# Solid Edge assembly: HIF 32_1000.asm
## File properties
Title: Zylinder
Author: ahadarics
Template: iso assembly.asm
Last saved by: ahadarics
Revision: 63
Application: Solid Edge
Username: ahadarics
Dokumentum tartalom típus: 1
Document Number: HIF 32/1000
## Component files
Prfilrohr 32_1000.par
Mutter.par
Kolbenstange 32_1000.par
Kit_1.par
Kit_2.par
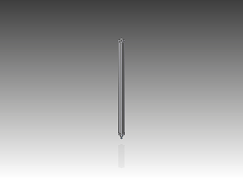
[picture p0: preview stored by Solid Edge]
